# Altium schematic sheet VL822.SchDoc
size A3; SheetNumber: 2; SheetTotal: 4
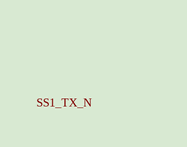
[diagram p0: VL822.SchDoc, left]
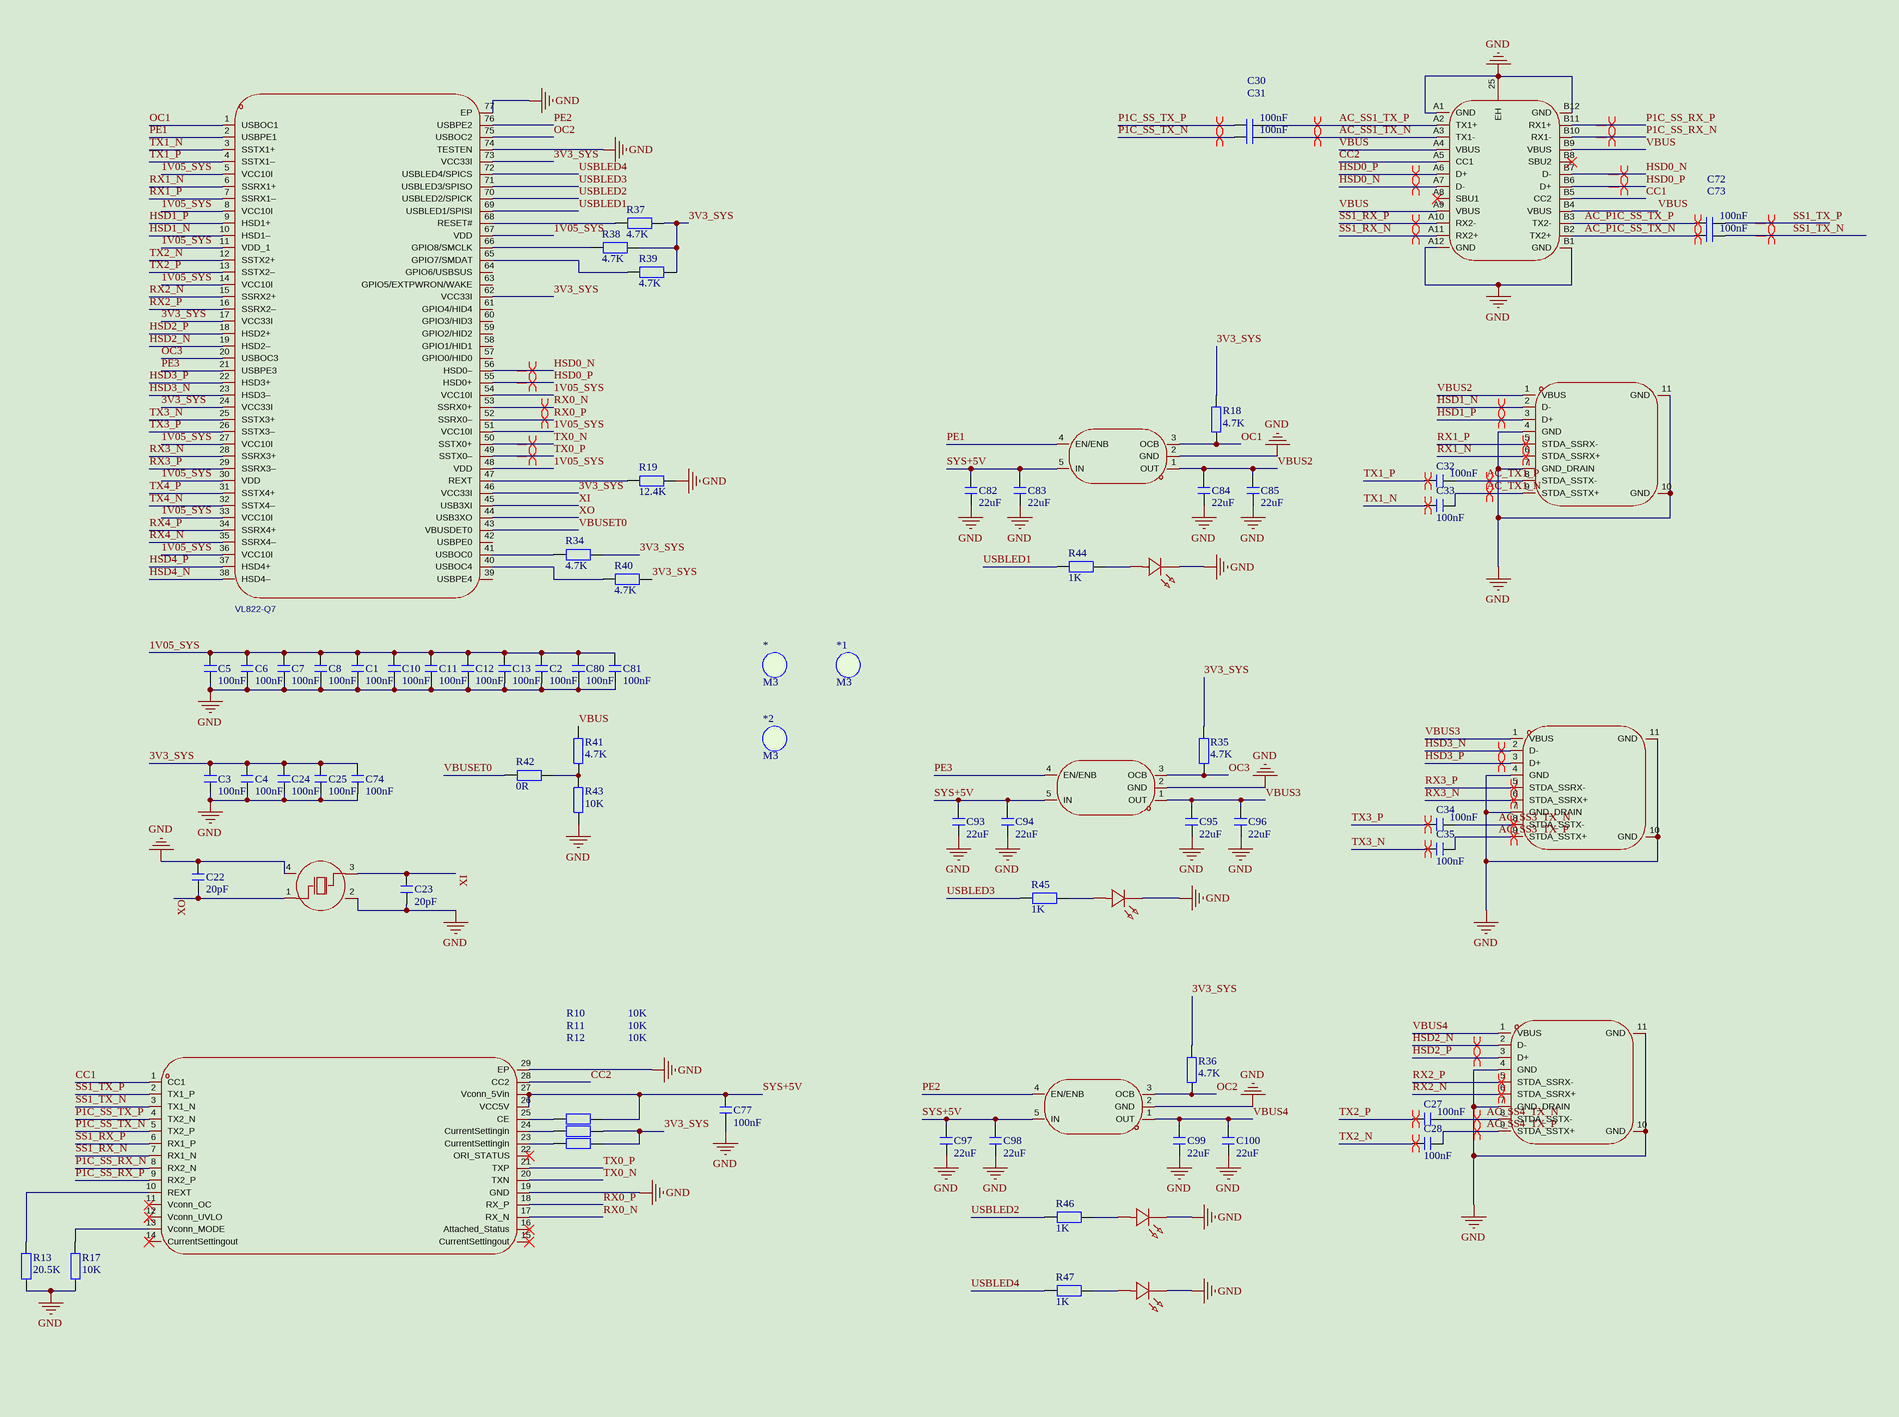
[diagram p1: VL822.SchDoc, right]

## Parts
*  M3  [M3 125X200]
*1  M3  [M3 125X200]
*2  M3  [M3 125X200]
C1  100nF  [C 0402_L]
C2  100nF  [C 0402_L]
C3  100nF  [C 0402_L]
C4  100nF  [C 0402_L]
C5  100nF  [C 0402_L]
C6  100nF  [C 0402_L]
C7  100nF  [C 0402_L]
C8  100nF  [C 0402_L]
C10  100nF  [C 0402_L]
C11  100nF  [C 0402_L]
C12  100nF  [C 0402_L]
C13  100nF  [C 0402_L]
C22  20pF  [C 0603_L]
C23  20pF  [C 0603_L]
C24  100nF  [C 0402_L]
C25  100nF  [C 0402_L]
C27  100nF  [C 0402_L]
C28  100nF  [C 0402_L]
C30  100nF  [C 0402_L]
C31  100nF  [C 0402_L]
C32  100nF  [C 0402_L]
C33  100nF  [C 0402_L]
C34  100nF  [C 0402_L]
C35  100nF  [C 0402_L]
C72  100nF  [C 0402_L]
C73  100nF  [C 0402_L]
C74  100nF  [C 0402_L]
C77  100nF  [C 0402_L]
C80  100nF  [C 0402_L]
C81  100nF  [C 0402_L]
C82  22uF  [C 0805_L]
C83  22uF  [C 0805_L]
C84  22uF  [C 0805_L]
C85  22uF  [C 0805_L]
C93  22uF  [C 0805_L]
C94  22uF  [C 0805_L]
C95  22uF  [C 0805_L]
C96  22uF  [C 0805_L]
C97  22uF  [C 0805_L]
C98  22uF  [C 0805_L]
C99  22uF  [C 0805_L]
C100  22uF  [C 0805_L]
LED1  f.0603.00025/p2-0603g1ts2-06t-002  [LED0603-RD_GREEN]  (value not drawn)
LED2  f.0603.00025/p2-0603g1ts2-06t-002  [LED0603-RD_GREEN]  (value not drawn)
LED3  f.0603.00025/p2-0603g1ts2-06t-002  [LED0603-RD_GREEN]  (value not drawn)
LED4  f.0603.00025/p2-0603g1ts2-06t-002  [LED0603-RD_GREEN]  (value not drawn)
R10  10K  [R 0402_L]
R11  10K  [R 0402_L]
R12  10K  [R 0402_L]
R13  20.5K  [R 0402_L]
R17  10K  [R 0402_L]
R18  4.7K  [R 0402_L]
R19  12.4K  [R 0402_L]
R34  4.7K  [R 0402_L]
R35  4.7K  [R 0402_L]
R36  4.7K  [R 0402_L]
R37  4.7K  [R 0402_L]
R38  4.7K  [R 0402_L]
R39  4.7K  [R 0402_L]
R40  4.7K  [R 0402_L]
R41  4.7K  [R 0402_L]
R42  0R  [R 0402_L]
R43  10K  [R 0402_L]
R44  1K  [R 0402_L]
R45  1K  [R 0402_L]
R46  1K  [R 0402_L]
R47  1K  [R 0402_L]
U1  sy6288caac  [SOT-23-5_L3.0-W1.7-P0.95-LS2.8-BR]  (value not drawn)
U3  vl822-q7  [QFN-76_L9.0-W9.0-P0.40-EP6.3-TL]
U7  sy6288caac  [SOT-23-5_L3.0-W1.7-P0.95-LS2.8-BR]  (value not drawn)
U16  vl162  [MQFN-28_L4.5-W3.5-P0.40-BL-EP]  (value not drawn)
U18  sy6288caac  [SOT-23-5_L3.0-W1.7-P0.95-LS2.8-BR]  (value not drawn)
USB1  hc-usb3.0-l168-zj  [USB3.0-A-TH_HC-USB3.0-L168-ZJ]  (value not drawn)
USB2  hc-usb3.0-l168-zj  [USB3.0-A-TH_HC-USB3.0-L168-ZJ]  (value not drawn)
USB3  type-c 24p qcht  [TYPE-C-SMD_TYPE-C-24P-QCHT]  (value not drawn)
USB4  hc-usb3.0-l168-zj  [USB3.0-A-TH_HC-USB3.0-L168-ZJ]  (value not drawn)
X1  x322525mob4si  [CRYSTAL-SMD_4P-L3.2-W2.5-BL]  (value not drawn)

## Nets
GND: C1.1 C2.1 C3.1 C4.1 C5.1 C6.1 C7.1 C8.1 C10.1 C11.1 C12.1 C13.1 C22.2 C23.1 C24.1 C25.1 C74.1 C77.1 C80.1 C81.1 C82.1 C83.1 C84.1 C85.1 C93.1 C94.1 C95.1 C96.1 C97.1 C98.1 C99.1 C100.1 LED1.1(C) LED2.1(C) LED3.1(C) LED4.1(C) R13.1 R17.1 R19.1 R43.2 U1.2(GND) U3.74(TESTEN) U3.77(EP) U7.2(GND) U16.19(GND) U16.29(EP) U18.2(GND) USB1.4(GND) USB1.7(GND_DRAIN) USB1.10(GND) USB1.11(GND) USB2.4(GND) USB2.7(GND_DRAIN) USB2.10(GND) USB2.11(GND) USB3.25(EH) USB3.A1(GND) USB3.A12(GND) USB3.B1(GND) USB3.B12(GND) USB4.4(GND) USB4.7(GND_DRAIN) USB4.10(GND) USB4.11(GND) X1.2(GND) X1.4(GND)
1V05_SYS: C1.2 C2.2 C5.2 C6.2 C7.2 C8.2 C10.2 C11.2 C12.2 C13.2 C80.2 C81.2 U3.5(VCC10I) U3.8(VCC10I) U3.11(VDD_1) U3.14(VCC10I) U3.27(VCC10I) U3.30(VDD) U3.33(VCC10I) U3.36(VCC10I) U3.48(VDD) U3.51(VCC10I) U3.54(VCC10I) U3.67(VDD)
3V3_SYS: C3.2 C4.2 C24.2 C25.2 C74.2 R10.2 R11.2 R18.1 R34.1 R35.1 R36.1 R37.1 R38.1 R39.1 R40.1 U3.17(VCC33I) U3.24(VCC33I) U3.46(VCC33I) U3.62(VCC33I) U3.73(VCC33I)
AC_P1C_SS_TX_N: C73.2 USB3.B2(TX2+)
AC_P1C_SS_TX_P: C72.2 USB3.B3(TX2-)
AC_SS1_TX_N: C31.1 USB3.A3(TX1-)
AC_SS1_TX_P: C30.1 USB3.A2(TX1+)
AC_SS3_TX_N: C34.1 USB2.8(STDA_SSTX-)
AC_SS3_TX_P: C35.1 USB2.9(STDA_SSTX+)
AC_SS4_TX_N: C27.1 USB4.8(STDA_SSTX-)
AC_SS4_TX_P: C28.1 USB4.9(STDA_SSTX+)
AC_TX1_N: C33.1 USB1.9(STDA_SSTX+)
AC_TX1_P: C32.1 USB1.8(STDA_SSTX-)
CC1: U16.1(CC1) USB3.B5(CC2)
CC2: U16.28(CC2) USB3.A5(CC1)
HSD0_N: U3.56(HSD0–) USB3.A7(D-) USB3.B7(D-)
HSD0_P: U3.55(HSD0+) USB3.A6(D+) USB3.B6(D+)
HSD1_N: U3.10(HSD1–) USB1.2(D-)
HSD1_P: U3.9(HSD1+) USB1.3(D+)
HSD2_N: U3.19(HSD2–) USB4.2(D-)
HSD2_P: U3.18(HSD2+) USB4.3(D+)
HSD3_N: U3.23(HSD3–) USB2.2(D-)
HSD3_P: U3.22(HSD3+) USB2.3(D+)
HSD4_N: U3.38(HSD4–)
HSD4_P: U3.37(HSD4+)
OC1: R18.2 U1.3(OCB) U3.1(USBOC1)
OC2: R36.2 U3.75(USBOC2) U18.3(OCB)
OC3: R35.2 U3.20(USBOC3) U7.3(OCB)
P1C_SS_RX_N: U16.8(RX2_N) USB3.B10(RX1-)
P1C_SS_RX_P: U16.9(RX2_P) USB3.B11(RX1+)
P1C_SS_TX_N: C31.2 U16.5(TX2_P)
P1C_SS_TX_P: C30.2 U16.4(TX2_N)
PE1: U1.4(EN/ENB) U3.2(USBPE1)
PE2: U3.76(USBPE2) U18.4(EN/ENB)
PE3: U3.21(USBPE3) U7.4(EN/ENB)
RX0_N: U3.53(SSRX0+) U16.17(RX_N)
RX0_P: U3.52(SSRX0–) U16.18(RX_P)
RX1_N: U3.6(SSRX1+) USB1.6(STDA_SSRX+)
RX1_P: U3.7(SSRX1–) USB1.5(STDA_SSRX-)
RX2_N: U3.15(SSRX2+) USB4.6(STDA_SSRX+)
RX2_P: U3.16(SSRX2–) USB4.5(STDA_SSRX-)
RX3_N: U3.28(SSRX3+) USB2.6(STDA_SSRX+)
RX3_P: U3.29(SSRX3–) USB2.5(STDA_SSRX-)
RX4_N: U3.35(SSRX4–)
RX4_P: U3.34(SSRX4+)
SS1_RX_N: U16.7(RX1_N) USB3.A11(RX2+)
SS1_RX_P: U16.6(RX1_P) USB3.A10(RX2-)
SS1_TX_N: C73.1 U16.3(TX1_N)
SS1_TX_P: C72.1 U16.2(TX1_P)
SYS+5V: C77.2 C82.2 C83.2 C93.2 C94.2 C97.2 C98.2 R12.2 U1.5(IN) U7.5(IN) U16.26(VCC5V) U16.27(Vconn_5Vin) U18.5(IN)
TX0_N: U3.50(SSTX0+) U16.20(TXN)
TX0_P: U3.49(SSTX0–) U16.21(TXP)
TX1_N: C33.2 U3.3(SSTX1+)
TX1_P: C32.2 U3.4(SSTX1–)
TX2_N: C28.2 U3.12(SSTX2+)
TX2_P: C27.2 U3.13(SSTX2–)
TX3_N: C35.2 U3.25(SSTX3+)
TX3_P: C34.2 U3.26(SSTX3–)
TX4_N: U3.32(SSTX4–)
TX4_P: U3.31(SSTX4+)
USBLED1: R44.2 U3.69(USBLED1/SPISI)
USBLED2: R46.2 U3.70(USBLED2/SPICK)
USBLED3: R45.2 U3.71(USBLED3/SPISO)
USBLED4: R47.2 U3.72(USBLED4/SPICS)
VBUS: R41.1 USB3.A4(VBUS) USB3.A9(VBUS) USB3.B4(VBUS) USB3.B9(VBUS)
VBUS2: C84.2 C85.2 U1.1(OUT) USB1.1(VBUS)
VBUS3: C95.2 C96.2 U7.1(OUT) USB2.1(VBUS)
VBUS4: C99.2 C100.2 U18.1(OUT) USB4.1(VBUS)
VBUSET0: R42.2 U3.43(VBUSDET0)
XI: C23.2 U3.45(USB3XI) X1.3(OSC2)
XO: C22.1 U3.44(USB3XO) X1.1(OSC1)
NetLED1_2: LED1.2(A) R44.1
NetLED2_2: LED2.2(A) R45.1
NetLED3_2: LED3.2(A) R46.1
NetLED4_2: LED4.2(A) R47.1
NetR10_1: R10.1 U16.23(CurrentSettingin)
NetR11_1: R11.1 U16.24(CurrentSettingin)
NetR12_1: R12.1 U16.25(CE)
NetR13_2: R13.2 U16.10(REXT)
NetR17_2: R17.2 U16.13(Vconn_MODE)
NetR19_2: R19.2 U3.47(REXT)
NetR34_2: R34.2 U3.41(USBOC0)
NetR37_2: R37.2 U3.68(RESET#)
NetR38_2: R38.2 U3.66(GPIO8/SMCLK)
NetR39_2: R39.2 U3.65(GPIO7/SMDAT)
NetR40_2: R40.2 U3.40(USBOC4)
NetR41_2: R41.2 R42.1 R43.1

Not connected (* = marked no-connect by the designer): U3 39(USBPE4) 42(USBPE0) 57(GPIO0/HID0) 58(GPIO1/HID1) 59(GPIO2/HID2) 60(GPIO3/HID3) 61(GPIO4/HID4) 63(GPIO5/EXTPWRON/WAKE) 64(GPIO6/USBSUS); U16 11(Vconn_OC)* 12(Vconn_UVLO)* 14(CurrentSettingout)* 15(CurrentSettingout)* 16(Attached_Status)* 22(ORI_STATUS)*; USB3 A8(SBU1)* B8(SBU2)*

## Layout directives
differential pair; differential pair class 90ohm: AC_P1C_SS_TX_N, AC_P1C_SS_TX_P, AC_SS1_TX_N, AC_SS1_TX_P, AC_SS3_TX_N, AC_SS3_TX_P, AC_SS4_TX_N, AC_SS4_TX_P, AC_TX1_N, AC_TX1_P, HSD0_N, HSD0_P, HSD1_N, HSD1_P, HSD2_N, HSD2_P, HSD3_N, HSD3_P, P1C_SS_RX_N, P1C_SS_RX_P, P1C_SS_TX_N, P1C_SS_TX_P, RX0_N, RX0_P, RX1_N, RX1_P, RX2_N, RX2_P, RX3_N, RX3_P, SS1_RX_N, SS1_RX_P, SS1_TX_N, SS1_TX_P, TX0_N, TX0_P, TX1_N, TX1_P, TX2_N, TX2_P, TX3_N, TX3_P

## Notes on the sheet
- Labels drawn without touching a wire or pin: SS1_TX_N

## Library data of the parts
* *1 *2 = M3: 铜柱孔; 版权归属: 源创客
C1-C8 C10-C13 C22-C25 C27 C28 C30-C35 C72-C74 C77 C80-C85 C93-C100 = C: 无极性贴片电容; 版权归属: 源创客; 材质: X7R
LED1-LED4 = f.0603.00025/p2-0603g1ts2-06t-002: 灯头类型:1.6mmx0.8mm方形灯头;发光颜色:翠绿色;正向压降(Vf):2.6V~2.9V;功率:90mW;正向电流:30mA;波长:520nm~525nm;二极管配置:独立二极管;透镜颜色:-;色温:-;发光强度:230mcd;发光角度:120°;载带方式:-;工作温度:-40℃~+85℃;; Manufacturer: TUOZHAN(拓展光电); AddInBom: yes; ModelId: 7761174b67d9475ab0dbce38062fb2f9; ModelTransform: 63.7794,31.496,0,0,0,0,0,0,0; Illumination Color: 翠绿色; Power(Watts): 90mW; Forward Current: 30mA; Peak Wavelength: 517nm; Diode Configuration: 独立二极管; Luminous Intensity: 230mcd; Viewing Angle: 120°
R10-R13 R17-R19 R34-R47 = R: 贴片电阻; 版权归属: 源创客
U1 U7 U18 = sy6288caac: 类型:负载开关;通道数:1;输入控制逻辑:高电平有效;工作电压:2.5V~5.5V;最大连续电流:2A;导通电阻:60mΩ;; Manufacturer: Silergy(矽力杰); AddInBom: yes; ModelId: 0a2a1b8f50944f73965918ad6e5fe167; ModelName: SOT-23-5_L2.9-W1.6-H1.1-LS2.8-P0.95; ModelTransform: 114.173,109.636,0,180,0,0,0,0,0; Number of Channels: 1; Control Input Logic: 高电平有效; Maximum Continuous Current: 2A; RDS(on): 60mΩ
U3 = vl822-q7: VL822是一款USB 3.1 Gen2集线器控制器，具有高度集成的专用应用设计。VL822有1个上游端口和4个/2个下游端口，所有端口均支持10Gbps的USB 3.1 Gen2操作。下游端口可支持超速+（10Gbps）、超速（5Gbps）、高速（480Mbps）、全速（12Mbps）和低速（1.5Mbps）设备的任意组合; Manufacturer: VIA Labs(威锋电子); AddInBom: yes; ModelId: cfb2f5f80e274f87b1df67cc6bc46959; ModelName: QFN-76_L9.0-W9.0-H0.9-P0.40-EP6.4-TL; ModelTransform: 354.33,354.33,0,0,0,0,0,0,0; USB Protocol: USB 3.1；USB 2.0; Data Rate: 480Mbps；10Gbps; Voltage - Supply: 0.95V~1.05V；3V~3.6V; Memory Interface: SPI; Number of Channels: 4
U16 = vl162: 特性：USB Type-C数据开关，带适用于USB 3.1 Gen2 (10 Gbps)的CC功能。 4:2 10Gbps USB Type-C数据开关。 支持高达10Gbps。应用：线缆+设备应用; Manufacturer: VIA Labs(威锋电子); AddInBom: yes; ModelId: b29b69759c5e47d881066d3712682f60; ModelTransform: 177.952,138.5824,0,0,0,0,0,0,0; USB Protocol: USB 3.1; Voltage - Supply: 4.5V~5.5V; Current - Supply: 1.2mA; Quiescent Supply Current: 0.5mA; Number of Channels: 2
USB1 USB2 USB4 = hc-usb3.0-l168-zj: 连接器类型:Type-A;协议标准:USB 3.0;公母:母;安装方式:弯插;触点数量:9P;端口数量:1;额定电流 - 电源:1.5A;工作温度:-25℃~+70℃;; Manufacturer: HC(虹成电子); AddInBom: yes; ModelId: bc0796d16d324bfcacd0bfc17bd253cb; ModelTransform: 566.928,661.41998,0,0,0,0,-0.001,-204.722,-114.173; Connector Type: Type-A; Protocol Standard: USB 3.0; Gender: 母; Number of Contacts: 9P; Number of Ports: 1; Current Rating-Power: 1.5A; Voltage Rating: 30V; Connect-Disconnect Life: 1.5千次; Detection color: 蓝色
USB3 = type-c 24p qcht: 连接器类型:Type-C;协议标准:USB 3.1;公母:母;安装方式:卧贴;触点数量:24P;端口数量:1;额定电流 - 电源:3A;工作温度:-40℃~+85℃;; Manufacturer: SHOU HAN(首韩); AddInBom: yes; ModelId: caecbdeb99a8472ba4a8af874d656e7a; ModelTransform: 379.5268,387.7945,0,0,0,0,0,-30.041,-47.244; Protocol Standard: USB 3.1; Gender: 母; Number of Ports: 1; Current Rating-Power: 3A; Voltage Rating: 30V; Connect-Disconnect Life: 1万次; Detection color: 黑色
X1 = x322525mob4si: 晶振类型:贴片晶振;频率:25MHz;常温频差:±10ppm;负载电容:12pF;频率稳定度:±20ppm;; Manufacturer: YXC(扬兴晶振); AddInBom: yes; ModelId: ff2dfd5650294453a14147960efe1838; ModelTransform: 125.984,98.425,0,0,0,0,0,0,0; Value: 25MHz; Normal temperature Frequency Tolerance: ±10ppm; Load Capacitance: 12pF; Frequency Stability: ±20ppm; Equivalent Series Resistance(ESR): 50Ω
